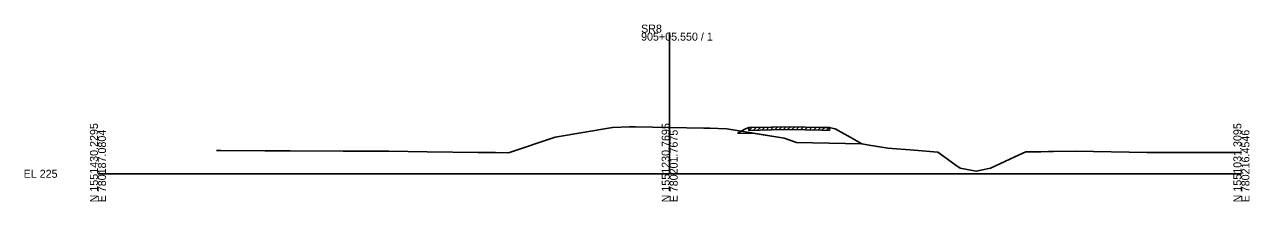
# Model space of a CAD drawing. Extents: x -26 to 787523, y -10 to 1545496.
# Drawn here: x -25.7 to 402.8, y 10490.3 to 10552.2 of the extents above; entities that cross this region are included whole.
import ezdxf

# ---------------------------------------------------------------- set-up
doc = ezdxf.new("R2010")
doc.units = 0
for name, color, linetype in [('50', 7, 'Continuous'), ('XS_CELL', 7, 'Continuous'), ('XS_M_SHAPES_EARTHWORK', 7, 'Continuous'), ('XS_P_FINISHED_GRADE', 7, 'Continuous'), ('XS_P_SUBGRADE_GRANULAR', 7, 'Continuous'), ('XS_X_GROUND', 7, 'Continuous')]:
    doc.layers.add(name, color=color, linetype=linetype)

msp = doc.modelspace()

# ---------------------------------------------------------------- linework, layer by layer
at = {"layer": '50'}
for p, q in [((230.71, 10515.2), (231.74, 10516.22)), ((232.22, 10515.23), (233.24, 10516.25)), ((233.72, 10515.26), (234.75, 10516.29)), ((235.23, 10515.3), (236.25, 10516.32)), ((236.73, 10515.33), (237.76, 10516.35)), ((238.24, 10515.37), (239.27, 10516.39)), ((239.74, 10515.4), (240.77, 10516.42)), ((241.25, 10515.43), (242.26, 10516.44)), ((242.75, 10515.43), (243.73, 10516.41)), ((244.26, 10515.4), (245.24, 10516.37)), ((245.76, 10515.36), (246.75, 10516.34)), ((247.27, 10515.33), (248.25, 10516.3)), ((248.77, 10515.29), (249.76, 10516.27)), ((250.28, 10515.26), (251.26, 10516.23)), ((251.79, 10515.22), (252.77, 10516.2)), ((227.7, 10515.13), (228.73, 10516.15)), ((227.7, 10515.13), (227.7, 10516.13)), ((227.7, 10515.13), (235.63, 10515.31)), ((229.21, 10515.16), (230.23, 10516.18)), ((235.63, 10515.31), (241.93, 10515.45)), ((241.93, 10515.45), (253.06, 10515.19)), ((253.06, 10515.19), (255.91, 10515.13)), ((253.29, 10515.19), (254.27, 10516.16)), ((254.8, 10515.15), (255.78, 10516.13)), ((255.91, 10516.13), (255.91, 10515.13))]:
    msp.add_line(p, q, dxfattribs=at)
at = {"layer": 'XS_CELL'}
for p, q in [((200, 10500), (200, 10549.35)), ((0, 10500), (200, 10500)), ((200, 10500), (400, 10500))]:
    msp.add_line(p, q, dxfattribs=at)
at = {"layer": 'XS_M_SHAPES_EARTHWORK'}
for points in [[(253.06, 10516.19), (255.91, 10516.13), (255.91, 10515.13), (253.06, 10515.19), (241.93, 10515.45), (235.63, 10515.31), (227.7, 10515.13), (227.7, 10516.13), (235.63, 10516.31), (241.93, 10516.45)], [(253.06, 10516.19), (255.91, 10516.13), (255.91, 10515.13), (253.06, 10515.19), (241.93, 10515.45), (235.63, 10515.31), (227.7, 10515.13), (227.7, 10516.13), (235.63, 10516.31), (241.93, 10516.45)], [(224.99, 10514.9), (229.81, 10514.1), (223.82, 10514.25)], [(224.99, 10514.9), (229.81, 10514.1), (223.82, 10514.25)], [(256.26, 10516.06), (257.92, 10515.73), (263.12, 10512.79), (267.18, 10510.49), (244.35, 10510.95), (240, 10512.4), (229.81, 10514.1), (224.99, 10514.9), (226.5, 10515.75), (227.15, 10515.95), (227.7, 10516.13), (227.7, 10515.13), (235.63, 10515.31), (241.93, 10515.45), (253.06, 10515.19), (255.91, 10515.13), (255.91, 10516.13)], [(255.91, 10516.13), (256.26, 10516.06), (257.92, 10515.73), (263.12, 10512.79), (267.18, 10510.49), (244.35, 10510.95), (240, 10512.4), (229.81, 10514.1), (224.99, 10514.9), (226.5, 10515.75), (227.15, 10515.95), (227.7, 10516.13), (227.7, 10515.13), (235.63, 10515.31), (241.93, 10515.45), (253.06, 10515.19), (255.91, 10515.13)]]:
    msp.add_lwpolyline(points, close=True, dxfattribs=at)
at = {"layer": 'XS_P_FINISHED_GRADE'}
for p, q in [((224.99, 10514.9), (240, 10512.4)), ((240, 10512.4), (244.35, 10510.95)), ((267.18, 10510.49), (244.35, 10510.95))]:
    msp.add_line(p, q, dxfattribs=at)
at = {"layer": 'XS_P_SUBGRADE_GRANULAR'}
for q in [(224.99, 10514.9), (229.81, 10514.1)]:
    msp.add_line((223.82, 10514.25), q, dxfattribs=at)
at = {"layer": 'XS_X_GROUND'}
for p, q in [((180, 10516.15), (186, 10516.39)), ((186, 10516.39), (188, 10516.36)), ((188, 10516.36), (200, 10516.18)), ((227.7, 10516.13), (235.63, 10516.31)), ((235.63, 10516.31), (241.93, 10516.45)), ((241.93, 10516.45), (253.06, 10516.19)), ((253.06, 10516.19), (255.91, 10516.13)), ((143.65, 10507.37), (160, 10512.82)), ((160, 10512.82), (180, 10516.15)), ((200, 10516.18), (212, 10516)), ((212, 10516), (214, 10515.97)), ((214, 10515.97), (220, 10515.73)), ((220, 10515.73), (224.99, 10514.9)), ((224.99, 10514.9), (226.5, 10515.75)), ((226.5, 10515.75), (227.15, 10515.95)), ((227.15, 10515.95), (227.7, 10516.13)), ((255.91, 10516.13), (256.26, 10516.06)), ((256.26, 10516.06), (257.92, 10515.73)), ((257.92, 10515.73), (263.12, 10512.79)), ((263.12, 10512.79), (267.18, 10510.49)), ((41.44, 10508.1), (42.34, 10508.1)), ((42.34, 10508.1), (42.99, 10508.09)), ((42.99, 10508.09), (58.42, 10508.03)), ((58.42, 10508.03), (67.27, 10507.99)), ((67.27, 10507.99), (85.79, 10507.91)), ((85.79, 10507.91), (89.94, 10507.89)), ((89.94, 10507.89), (101.73, 10507.85)), ((101.73, 10507.85), (115.15, 10507.69)), ((115.15, 10507.69), (132.96, 10507.46)), ((267.18, 10510.49), (269.06, 10510.17)), ((269.06, 10510.17), (276.29, 10508.93)), ((276.29, 10508.93), (285.58, 10508.2)), ((285.58, 10508.2), (293.79, 10507.55)), ((322.32, 10506.6), (324.56, 10507.65)), ((324.56, 10507.65), (325.16, 10507.65)), ((325.16, 10507.65), (329.88, 10507.7)), ((329.88, 10507.7), (332.57, 10507.73)), ((332.57, 10507.73), (334.31, 10507.75)), ((334.31, 10507.75), (342.13, 10507.85)), ((342.13, 10507.85), (366.93, 10507.47)), ((132.96, 10507.46), (135.67, 10507.43)), ((135.67, 10507.43), (139.09, 10507.38)), ((139.09, 10507.38), (143.65, 10507.37)), ((293.79, 10507.55), (299.72, 10503.26)), ((312.27, 10501.92), (322.32, 10506.6)), ((366.93, 10507.47), (379.36, 10507.43)), ((379.36, 10507.43), (400, 10507.45)), ((299.72, 10503.26), (301.59, 10501.94)), ((301.59, 10501.94), (305.92, 10501.2)), ((305.92, 10501.2), (307.38, 10500.95)), ((307.38, 10500.95), (308.88, 10501.25)), ((308.88, 10501.25), (312.27, 10501.92))]:
    msp.add_line(p, q, dxfattribs=at)

# ---------------------------------------------------------------- texts
at = {"layer": 'XS_CELL'}
for s, p in [('SR8', (190, 10549.35)), ('905+05.550 / 1', (190, 10546.55)), ('EL 225', (-26, 10498.6))]:
    msp.add_text(s, height=2.8, dxfattribs=at).set_placement(p)
for s, p in [('N 1551430.2295', (0, 10490)), ('N 1551230.7695', (200, 10490)), ('N 1551031.3095', (400, 10490)), ('E 780187.0804', (2.8, 10490)), ('E 780201.7675', (202.8, 10490)), ('E 780216.4546', (402.8, 10490))]:
    msp.add_text(s, height=2.8, rotation=90, dxfattribs=at).set_placement(p)

doc.saveas('drawing.dxf')
